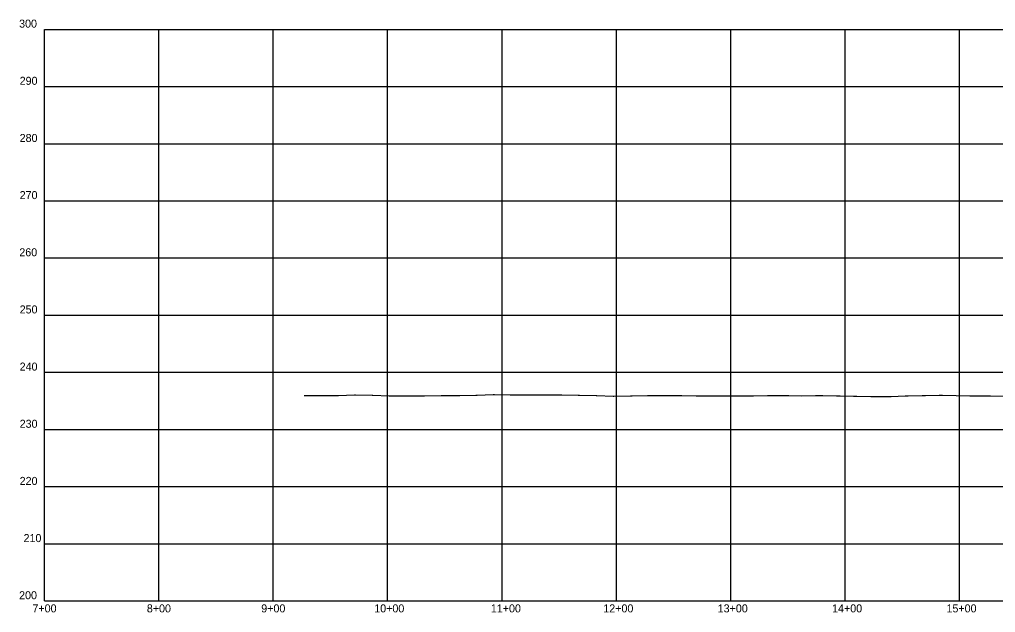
# Model space of a CAD drawing. Extents: x 976639 to 985448, y 1524031 to 1526806.
# Drawn here: x 976988 to 977841, y 1524043 to 1524562 of the extents above; entities that cross this region are included whole.
import ezdxf

# ---------------------------------------------------------------- set-up
doc = ezdxf.new("R2010")
doc.units = 0
for name, color, linetype in [('Default', 7, 'Continuous'), ('R_Axis', 7, 'Continuous'), ('R_Axis Annot', 7, 'Continuous'), ('R_Grid', 7, 'Continuous')]:
    doc.layers.add(name, color=color, linetype=linetype)

msp = doc.modelspace()

# ---------------------------------------------------------------- linework, layer by layer
at = {"layer": 'Default'}
msp.add_lwpolyline([(977236.32, 1524233.34), (977250.49, 1524233.17), (977251.32, 1524233.17), (977265.56, 1524233.34), (977266.32, 1524233.34), (977280.38, 1524233.73), (977281.32, 1524233.74), (977295.63, 1524233.4), (977296.32, 1524233.4), (977310.7, 1524232.87), (977311.32, 1524232.88), (977325.83, 1524232.79), (977326.32, 1524232.79), (977326.82, 1524232.79), (977341.45, 1524232.88), (977356.2, 1524233.13), (977356.45, 1524233.13), (977356.71, 1524233.13), (977371.45, 1524233.32), (977372.53, 1524233.32), (977386.45, 1524233.61), (977387.68, 1524233.61), (977401.46, 1524233.98), (977402.83, 1524233.97), (977416.33, 1524233.85), (977429.9, 1524233.73), (977431.33, 1524233.73), (977432.79, 1524233.73), (977446.33, 1524233.92), (977460.22, 1524233.85), (977461.47, 1524233.84), (977475.84, 1524233.44), (977476.47, 1524233.44), (977477.11, 1524233.43), (977491.47, 1524233.2), (977492.05, 1524233.2), (977506.48, 1524232.75), (977506.97, 1524232.75), (977521.47, 1524233.03), (977522.96, 1524233.04), (977536.47, 1524233.1), (977548.87, 1524233.22), (977551.38, 1524233.2), (977553.9, 1524233.21), (977566.38, 1524233.11), (977578.86, 1524233.02), (977581.38, 1524233.01), (977593.85, 1524232.94), (977596.38, 1524232.93), (977598.9, 1524232.92), (977611.38, 1524232.99), (977623.79, 1524233.03), (977626.44, 1524233.02), (977629.07, 1524233.02), (977641.44, 1524233.12), (977644.76, 1524233.1), (977656.44, 1524233.06), (977659.9, 1524233.08), (977671.44, 1524233.02), (977683.19, 1524233.06), (977686.44, 1524233.07), (977689.68, 1524233.08), (977701.55, 1524232.88), (977704.78, 1524232.93), (977716.55, 1524232.69), (977719.55, 1524232.71), (977731.55, 1524232.4), (977734.55, 1524232.38), (977746.55, 1524232.3), (977749.48, 1524232.29), (977761.55, 1524233.01), (977764.33, 1524233.01), (977776.55, 1524233.09), (977779.32, 1524233.08), (977791.31, 1524233.46), (977794.23, 1524233.45), (977806.31, 1524233.08), (977818.13, 1524232.99), (977821.31, 1524232.98), (977824.56, 1524232.99), (977836.31, 1524232.94), (977847.88, 1524232.64)], dxfattribs=at)
at = {"layer": 'R_Axis'}
for q in [(977009.31, 1524553.49), (979809.31, 1524053.49)]:
    msp.add_line((977009.31, 1524053.49), q, dxfattribs=at)
at = {"layer": 'R_Grid'}
for p, q in [((977009.31, 1524553.49), (979809.31, 1524553.49)), ((977009.31, 1524553.49), (979809.31, 1524553.49)), ((977109.31, 1524053.49), (977109.31, 1524553.49)), ((977209.31, 1524053.49), (977209.31, 1524553.49)), ((977309.31, 1524053.49), (977309.31, 1524553.49)), ((977409.31, 1524053.49), (977409.31, 1524553.49)), ((977509.31, 1524053.49), (977509.31, 1524553.49)), ((977609.31, 1524053.49), (977609.31, 1524553.49)), ((977709.31, 1524053.49), (977709.31, 1524553.49)), ((977809.31, 1524053.49), (977809.31, 1524553.49)), ((977009.31, 1524503.49), (979809.31, 1524503.49)), ((977009.31, 1524453.49), (979809.31, 1524453.49)), ((977009.31, 1524403.49), (979809.31, 1524403.49)), ((977009.31, 1524353.49), (979809.31, 1524353.49)), ((977009.31, 1524303.49), (979809.31, 1524303.49)), ((977009.31, 1524253.49), (979809.31, 1524253.49)), ((977009.31, 1524203.49), (979809.31, 1524203.49)), ((977009.31, 1524153.49), (979809.31, 1524153.49)), ((977009.31, 1524103.49), (979809.31, 1524103.49))]:
    msp.add_line(p, q, dxfattribs=at)

# ---------------------------------------------------------------- texts
at = {"layer": 'R_Axis Annot'}
for s, height, p in [('300', 7, (976987.14, 1524554.99)), ('300', 7, (976987.14, 1524554.99)), ('290', 7, (976987.62, 1524504.99)), ('280', 7, (976987.62, 1524454.99)), ('270', 7, (976987.62, 1524404.99)), ('260', 7, (976987.33, 1524354.99)), ('250', 7, (976987.62, 1524304.99)), ('240', 7, (976987.62, 1524254.99)), ('230', 7, (976987.62, 1524204.99)), ('220', 7, (976987.62, 1524154.99)), ('210', 7, (976991.02, 1524104.99)), ('200', 7, (976987.14, 1524054.99)), ('7+00', 7, (976998.8, 1524043.49)), ('-', 0.0001, (977009.31, 1524053.49)), ('8+00', 7, (977098.8, 1524043.49)), ('9+00', 7, (977198.8, 1524043.49)), ('10+00', 7, (977297.57, 1524043.49)), ('11+00', 7, (977399.51, 1524043.49)), ('12+00', 7, (977497.8, 1524043.49)), ('13+00', 7, (977597.8, 1524043.49)), ('14+00', 7, (977697.8, 1524043.49)), ('15+00', 7, (977797.8, 1524043.49))]:
    msp.add_text(s, height=height, dxfattribs=at).set_placement(p)

doc.saveas('drawing.dxf')
